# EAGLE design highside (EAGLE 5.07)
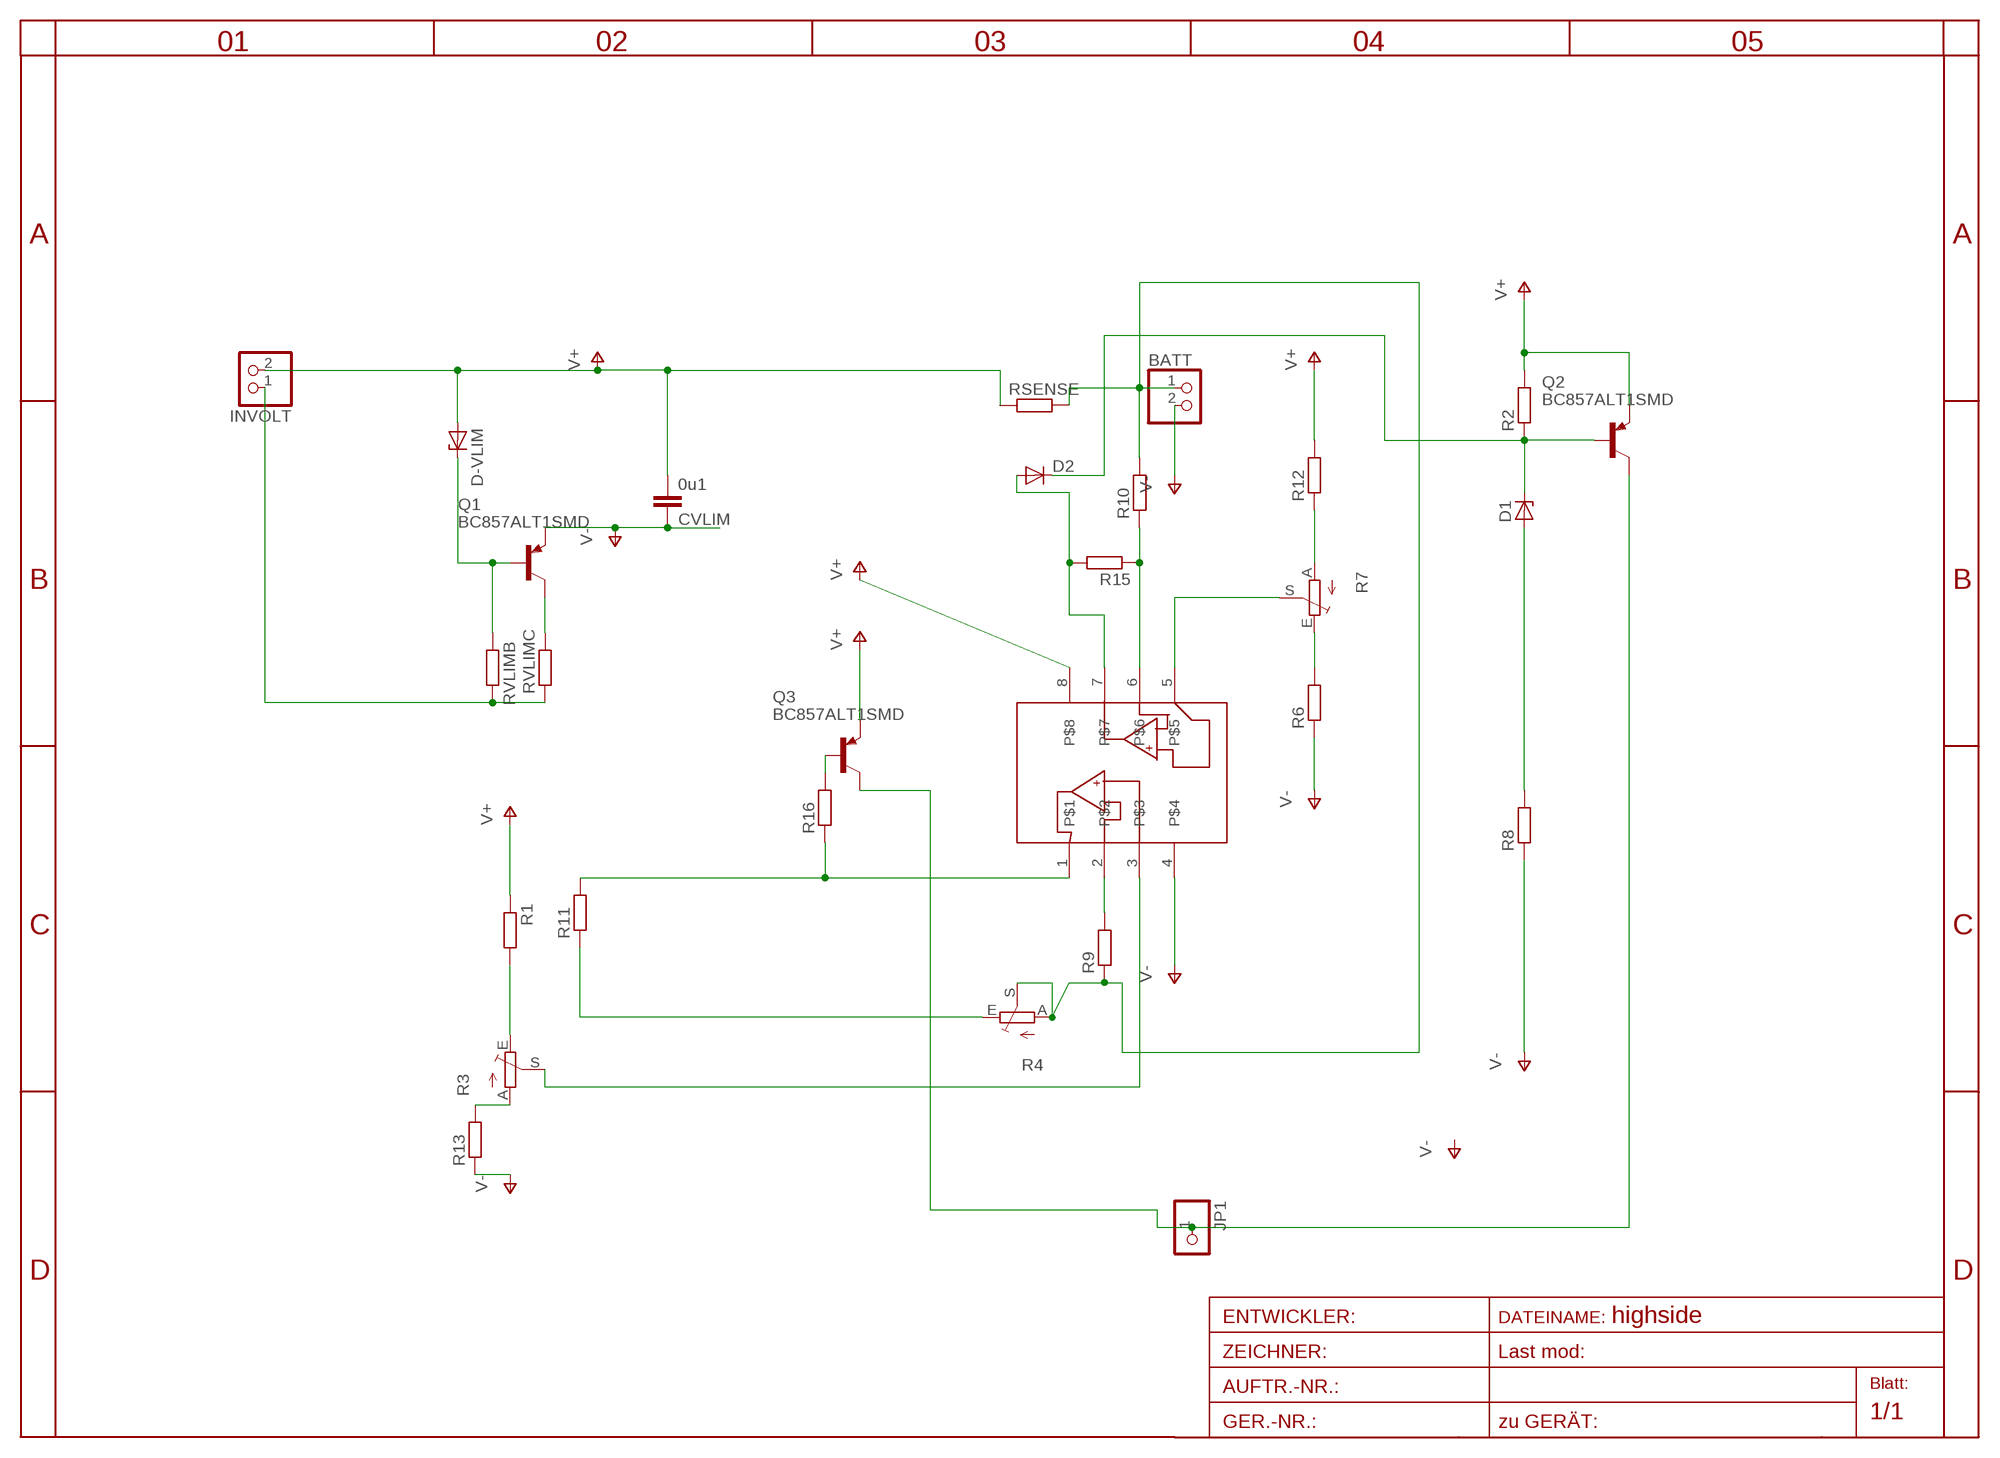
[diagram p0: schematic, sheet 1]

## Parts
BATT  PINHD-1X2  [1X02X05]
CVLIM  0u1  C-EUC1206  [C1206]
D1  ZENER-DIODESOD80C  [SOD80C]
D2  DIODE-SOD80C  [SOD80C]
D-VLIM  ZENER-DIODESOD80C  [SOD80C]
INVOLT  PINHD-1X2  [1X02X05]
JP1  PINHD-1X11X0.4  [1X01]
Q1  BC857ALT1SMD  [SOT23-BEC]
Q2  BC857ALT1SMD  [SOT23-BEC]
Q3  BC857ALT1SMD  [SOT23-BEC]
R1  R-EU_R0805  [R0805]
R2  R-EU_R0805  [R0805]
R3  TRIM_EU-CA6V  [CA6V]
R4  TRIM_EU-CA6V  [CA6V]
R6  R-EU_R0805  [R0805]
R7  TRIM_EU-CA6V  [CA6V]
R8  R-EU_R0805  [R0805]
R9  R-EU_R0805  [R0805]
R10  R-EU_R0805  [R0805]
R11  R-EU_R0805  [R0805]
R12  R-EU_R0805  [R0805]
R13  R-EU_R0805  [R0805]
R15  R-EU_R0805  [R0805]
R16  R-EU_R0805  [R0805]
RSENSE  R-EU_0204/2V  [0204V]
RVLIMB  R-EU_R0805  [R0805]
RVLIMC  R-EU_R0805  [R0805]
U$1  MCP6042SOIC  [SO-08]

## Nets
N$2: INVOLT.1 RVLIMB.2 RVLIMC.1
N$3: BATT.1 R4.A R4.S R9.1 R10.2 RSENSE.2
N$4: R10.1 R15.1 U$1.6
N$5: Q1.C RVLIMC.2
N$6: D-VLIM.C Q1.B RVLIMB.1
N$7: R4.E R11.1
N$8: R3.A R13.2
N$9: R9.2 U$1.2
N$10: R7.A R12.1
N$11: R6.2 R7.E
N$12: R7.S U$1.5
N$13: R11.2 R16.1 U$1.1
N$14: R1.2 R3.E
N$15: R3.S U$1.3
N$16: D1.A R8.2
N$17: D1.C D2.C Q2.B R2.1
N$19: D2.A R15.2 U$1.7
N$20: Q3.B R16.2
N$21: JP1.1 Q2.C Q3.C
V+: CVLIM.2 D-VLIM.A INVOLT.2 Q2.E Q3.E R1.1 R2.2 R12.2 RSENSE.1 U$1.8
V-: BATT.2 CVLIM.1 Q1.E R6.1 R8.1 R13.1 U$1.4

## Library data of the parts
BATT INVOLT = pinhead:PINHD-1X2: PIN HEADER
CVLIM = rcl:C-EU: CAPACITOR, European symbol
D1 D-VLIM = diode:ZENER-DIODE: Z-Diode
D2 = diode:DIODE-: DIODE
JP1 = pinhead:PINHD-1X1: PIN HEADER
Q1-Q3 = transistor-pnp:BC857*: PNP Transistror
R1 R2 R6 R8-R10 R12 R13 R15 RSENSE RVLIMB = rcl:R-EU_: RESISTOR, European symbol
R3 R4 R7 = pot:TRIM_EU-: POTENTIOMETER
R11 R16 RVLIMC = rcl-2:R-EU_: RESISTOR, European symbol
U$1 = microchip-3:MCP6042

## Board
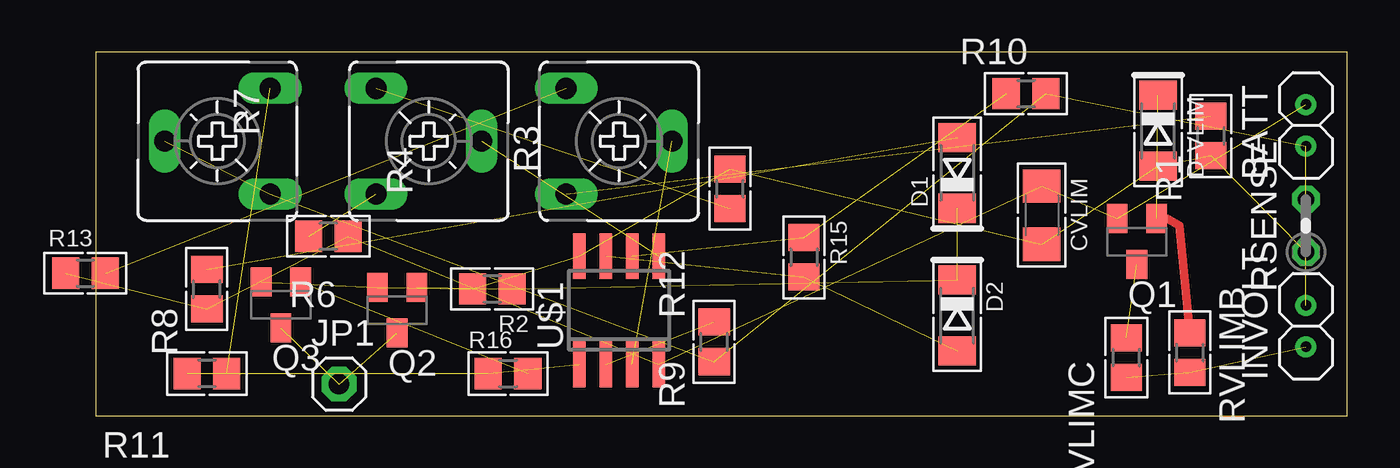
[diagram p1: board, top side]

Size 60.16 x 17.5 mm. Coordinates in mm from the lower left corner, seen from the top.
Outline: 0,0 60.16,0 60.16,17.5 0,17.5 0,0
Copper layers (1*16): Top 0.035mm / dielectric 1.5mm / Bottom 0.035mm
Design rules "default": minimum track width 20mil, minimum drill 24mil, track to track 20mil, track to pad 20mil, pad to pad 8mil, via to via 8mil, smd to smd 8mil, copper to edge 40mil, drill to drill 8mil, minimum pad ring 10mil, minimum via ring 8mil, stop-mask expansion 4mil, vias tented up to drill 0mil, thermal gap 10mil

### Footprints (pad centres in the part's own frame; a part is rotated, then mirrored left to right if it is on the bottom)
1X02X05 = drill 0.5 pad 0.813 round: 1 -1,0; 2 1,0
C1206 = smd 1.6 x 1.8: 1 -1.4,0; 2 1.4,0
SOD80C = smd 1.4 x 1.8: A 1.7,0; C -1.7,0
1X01 = drill 1 pad 1.676 octagon: 1 0,0
SOT23-BEC = smd 1 x 1.4: B -0.95,-1.1; C 0,1.1; E 0.95,-1.1
R0805 = smd 1.3 x 1.5: 1 -0.95,0; 2 0.95,0
CA6V = drill 1.016 long: A -2.54,-2.54; E 2.54,-2.54; S 0,2.54
0204V = drill 0.813 octagon: 1 -1.27,0; 2 1.27,0
SO-08 = smd 0.6 x 2.2: 1 -1.905,-2.6; 2 -0.635,-2.6; 3 0.635,-2.6; 4 1.905,-2.6; 5 1.905,2.6; 6 0.635,2.6; 7 -0.635,2.6; 8 -1.905,2.6

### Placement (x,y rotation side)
BATT  58.17,13.97 90 top
CVLIM  45.47,9.65 270 top
D1  41.4,11.68 90 top
D2  41.4,4.83 270 top
D-VLIM  51.05,13.72 270 top
INVOLT  58.17,4.32 90 top
JP1  11.68,1.52 0 top
Q1  50.04,8.38 180 top
Q2  14.48,5.08 180 top
Q3  8.89,5.33 180 top
R1  53.59,13.46 90 top
R2  19.05,6.1 180 top
R3  25.15,13.21 270 top
R4  5.84,13.21 90 top
R6  11.18,8.64 180 top
R7  16,13.21 270 top
R8  5.33,6.1 90 top
R9  29.72,3.56 90 top
R10  44.7,15.49 0 top
R11  5.33,2.03 180 top
R12  30.48,10.92 90 top
R13  -0.51,6.86 0 top
R15  34.04,7.62 270 top
R16  19.81,2.03 0 top
RSENSE  58.17,9.14 90 top
RVLIMB  52.58,3.05 270 top
RVLIMC  49.53,2.79 90 top
U$1  25.15,5.08 0 top

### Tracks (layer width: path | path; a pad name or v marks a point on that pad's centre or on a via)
N$2  (2 unrouted)
N$3  (5 unrouted)
N$4  (2 unrouted)
N$5  (1 unrouted)
N$6  (1 unrouted)
  Top 0.406: Q1.B 51.48,9.48 52.07,9.14 RVLIMB.1
N$7  (1 unrouted)
N$8  (1 unrouted)
N$9  (1 unrouted)
N$10  (1 unrouted)
N$11  (1 unrouted)
N$12  (1 unrouted)
N$13  (2 unrouted)
N$14  (1 unrouted)
N$15  (1 unrouted)
N$16  (1 unrouted)
N$17  (3 unrouted)
N$19  (2 unrouted)
N$20  (1 unrouted)
N$21  (2 unrouted)
V+  (9 unrouted)
V-  (6 unrouted)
